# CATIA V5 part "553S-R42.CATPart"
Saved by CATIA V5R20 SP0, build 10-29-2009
Part number: 553S-R42
Definition: NONE
Nomenclature: 553S-R42
Source: Unknown
Description: 553S-R42
Bounding box of the stored display mesh (mm): x -22.75 to 22.75, y -24.5 to 24.495, z -0.875 to 0.875
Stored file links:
  C:\Users\Utente\Desktop\IO LAVORO\3D X SITO CF\X SITO\PLASTICA\553S\553S-R42.CATPart
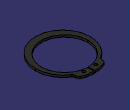
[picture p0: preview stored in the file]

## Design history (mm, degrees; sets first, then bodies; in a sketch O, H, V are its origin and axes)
Body1 "553S-R42" (main body)
  Solid1: solid without history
